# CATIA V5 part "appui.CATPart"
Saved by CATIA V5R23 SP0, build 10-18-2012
Part number: appui
Bounding box of the stored display mesh (mm): x -19.995 to 19.995, y -5 to 5, z -19.979 to 19.979
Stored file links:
  C:\wamp\www\COURS\CONCEPTION GMP1\TITRE 01-CATIA VOLUMIQUE\05--ACTIONNEUR DE VANNE\prof\CORRECTION\Assemblage\appui.CATPart
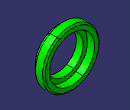
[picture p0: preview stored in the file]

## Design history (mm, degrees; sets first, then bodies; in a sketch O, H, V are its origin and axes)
Body1 (main body)
  Sketch1 on yz-plane, origin (0, 0, 0), H (0, 1, 0), V (0, 0, 1)
    line L1 (-5, 13) -> (-5, 16)
    point P2 (-5, 16)
    line L2 (-5, 16) -> (-1, 20)
    line L3 (-1, 20) -> (4, 20)
    point P4 (4, 20)
    line L4 (4, 20) -> (5, 19)
    point P5 (5, 19)
    line L5 (5, 19) -> (5, 16)
    line L6 (5, 16) -> (0, 16)
    line L7 (0, 16) -> (0, 13)
    line L8 (0, 13) -> (-5, 13)
    axis line L9 (0, 0) -> (85.5075, 0)
    distance L9 L8 = 13
    distance L6 L9 = 16
    angle L3 L4 = 45
    angle L2 L3 = 45
    distance L1 L7 = 5
    distance L7 L5 = 5
    distance L9 L3 = 20
    distance P4 P5 H = 1
    distance P2 L3 = 4
    vertical: L1 V, L5 V, L7 V
    horizontal: L3 H, L6 H, L8 H, L9 H
    coincidence: L7 V
  Shaft1: profile Sketch1, axis Sketch1.L9, angle 360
